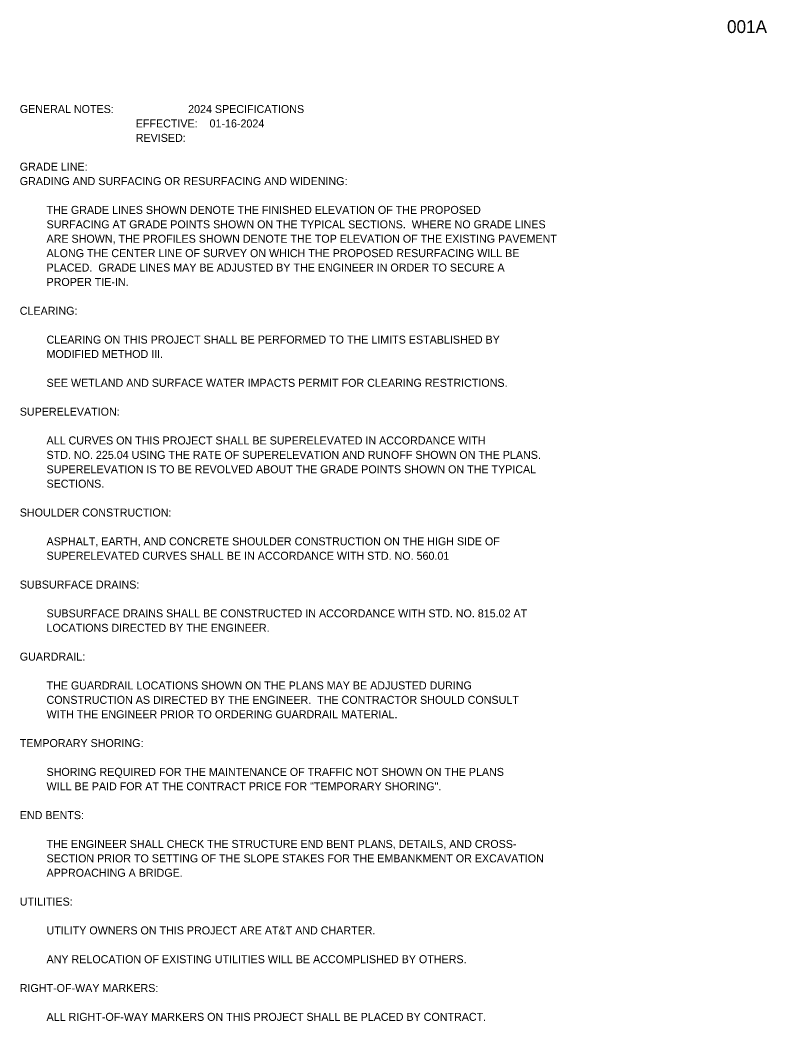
# Model space of a CAD drawing. Extents: x 2030341 to 2032444, y 1407825 to 1408818.
# Drawn here: x 2031744 to 2032444, y 1407867 to 1408805 of the extents above; entities that cross this region are included whole.
import ezdxf

# ---------------------------------------------------------------- set-up
doc = ezdxf.new("R2010")
doc.units = 0
doc.layers.add('Sheet_Data_Text_CELL', color=7, linetype='Continuous')
doc.layers.add('Sheet_Title_Block_Text', color=7, linetype='Continuous')

msp = doc.modelspace()

# ---------------------------------------------------------------- texts
at = {"layer": 'Sheet_Data_Text_CELL'}
for s, p in [('GENERAL NOTES:                         2024 SPECIFICATIONS', (2031743.97, 1408717.74)), ('                                       EFFECTIVE:    01-16-2024', (2031743.97, 1408704.24)), ('                                       REVISED:      ', (2031743.97, 1408690.74)), ('GRADE LINE:  ', (2031743.97, 1408663.74)), ('GRADING AND SURFACING OR RESURFACING AND WIDENING: ', (2031743.97, 1408650.24)), ('         THE GRADE LINES SHOWN DENOTE THE FINISHED ELEVATION OF THE PROPOSED ', (2031743.97, 1408623.24)), ('         SURFACING AT GRADE POINTS SHOWN ON THE TYPICAL SECTIONS.  WHERE NO GRADE LINES ', (2031743.97, 1408609.74)), ('         ARE SHOWN, THE PROFILES SHOWN DENOTE THE TOP ELEVATION OF THE EXISTING PAVEMENT ', (2031743.97, 1408596.24)), ('         ALONG THE CENTER LINE OF SURVEY ON WHICH THE PROPOSED RESURFACING WILL BE', (2031743.97, 1408582.74)), ('         PLACED.  GRADE LINES MAY BE ADJUSTED BY THE ENGINEER IN ORDER TO SECURE A ', (2031743.97, 1408569.24)), ('         PROPER TIE-IN. ', (2031743.97, 1408555.74)), ('CLEARING:  ', (2031743.97, 1408528.74)), ('         CLEARING ON THIS PROJECT SHALL BE PERFORMED TO THE LIMITS ESTABLISHED BY ', (2031743.97, 1408501.74)), ('         MODIFIED METHOD III.', (2031743.97, 1408488.24)), ('         SEE WETLAND AND SURFACE WATER IMPACTS PERMIT FOR CLEARING RESTRICTIONS. ', (2031743.97, 1408461.24)), ('SUPERELEVATION:  ', (2031743.97, 1408434.24)), ('         ALL CURVES ON THIS PROJECT SHALL BE SUPERELEVATED IN ACCORDANCE WITH', (2031743.97, 1408407.24)), ('         STD. NO. 225.04 USING THE RATE OF SUPERELEVATION AND RUNOFF SHOWN ON THE PLANS.', (2031743.97, 1408393.74)), ('         SUPERELEVATION IS TO BE REVOLVED ABOUT THE GRADE POINTS SHOWN ON THE TYPICAL ', (2031743.97, 1408380.24)), ('         SECTIONS.  ', (2031743.97, 1408366.74)), ('SHOULDER CONSTRUCTION:  ', (2031743.97, 1408339.74)), ('         ASPHALT, EARTH, AND CONCRETE SHOULDER CONSTRUCTION ON THE HIGH SIDE OF', (2031743.97, 1408312.74)), ('         SUPERELEVATED CURVES SHALL BE IN ACCORDANCE WITH STD. NO. 560.01', (2031743.97, 1408299.24)), ('SUBSURFACE DRAINS:', (2031743.97, 1408272.24)), ('         SUBSURFACE DRAINS SHALL BE CONSTRUCTED IN ACCORDANCE WITH STD. NO. 815.02 AT ', (2031743.97, 1408245.24)), ('         LOCATIONS DIRECTED BY THE ENGINEER.  ', (2031743.97, 1408231.74)), ('GUARDRAIL:  ', (2031743.97, 1408204.74)), ('         THE GUARDRAIL LOCATIONS SHOWN ON THE PLANS MAY BE ADJUSTED DURING ', (2031743.97, 1408177.74)), ('         CONSTRUCTION AS DIRECTED BY THE ENGINEER.  THE CONTRACTOR SHOULD CONSULT', (2031743.97, 1408164.24)), ('         WITH THE ENGINEER PRIOR TO ORDERING GUARDRAIL MATERIAL.', (2031743.97, 1408150.74)), ('TEMPORARY SHORING:  ', (2031743.97, 1408123.74)), ('         SHORING REQUIRED FOR THE MAINTENANCE OF TRAFFIC NOT SHOWN ON THE PLANS ', (2031743.97, 1408096.74)), ('         WILL BE PAID FOR AT THE CONTRACT PRICE FOR "TEMPORARY SHORING".', (2031743.97, 1408083.24)), ('END BENTS:  ', (2031743.97, 1408056.24)), ('         THE ENGINEER SHALL CHECK THE STRUCTURE END BENT PLANS, DETAILS, AND CROSS-', (2031743.97, 1408029.24)), ('         SECTION PRIOR TO SETTING OF THE SLOPE STAKES FOR THE EMBANKMENT OR EXCAVATION ', (2031743.97, 1408015.74)), ('         APPROACHING A BRIDGE.  ', (2031743.97, 1408002.24)), ('UTILITIES:  ', (2031743.97, 1407975.24)), ('         UTILITY OWNERS ON THIS PROJECT ARE AT&T AND CHARTER.', (2031743.97, 1407948.24)), ('         ANY RELOCATION OF EXISTING UTILITIES WILL BE ACCOMPLISHED BY OTHERS.  ', (2031743.97, 1407921.24)), ('RIGHT-OF-WAY MARKERS:  ', (2031743.97, 1407894.24)), ('         ALL RIGHT-OF-WAY MARKERS ON THIS PROJECT SHALL BE PLACED BY CONTRACT.  ', (2031743.97, 1407867.24))]:
    msp.add_text(s, height=7.5, dxfattribs=at).set_placement(p)
at = {"layer": 'Sheet_Title_Block_Text'}
msp.add_text('001A', height=12, dxfattribs=at).set_placement((2032406.51, 1408792.71))

doc.saveas('drawing.dxf')
